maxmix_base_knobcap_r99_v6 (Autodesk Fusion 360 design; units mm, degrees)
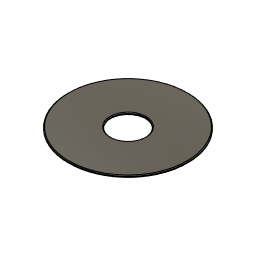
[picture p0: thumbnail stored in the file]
sketch "Sketch1" plane through (0, 0, 0) normal (0, 0, 1) x axis (1, 0, 0)
  circle C1 centre (0, 0) radius 17.45
  circle C2 centre (0, 0) radius 5.05
  point P1 (0, 0)
  point P2 (0, 0)
  point P3 (0, 0)
  coincident P1 P2
  coincident P1 P3
  dimension "d1" diameter C1 = 34.9
  dimension "d2" diameter C2 = 10.1
extrude "Extrude1" new body sketch "Sketch1" along normal blind 0.6
chamfer "Chamfer1" distance 0.2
